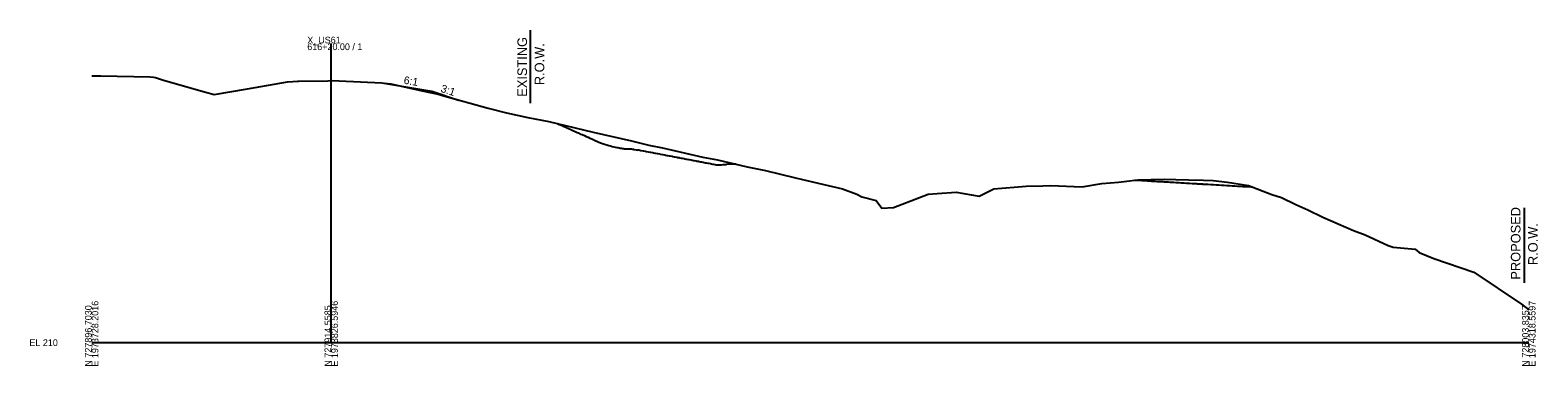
# Model space of a CAD drawing. Extents: x -26 to 1604, y -13 to 9623.
# Drawn here: x 974 to 1604, y 490 to 631 of the extents above; entities that cross this region are included whole.
import ezdxf

# ---------------------------------------------------------------- set-up
doc = ezdxf.new("R2010")
doc.units = 0
for name, color, linetype in [('Default', 7, 'Continuous'), ('Draft_XS_Grid', 7, 'Continuous'), ('DTM_X_GROUND', 7, 'Continuous'), ('SLOPE_STAKES_FILL', 7, 'Continuous'), ('XS_CELL', 7, 'Continuous'), ('XS_P_GROUND', 7, 'Continuous'), ('XS_P_ROW', 7, 'Continuous'), ('XS_P_TX_FS_BS', 7, 'Continuous'), ('XS_X_ROW', 7, 'Continuous')]:
    doc.layers.add(name, color=color, linetype=linetype)

msp = doc.modelspace()

# ---------------------------------------------------------------- linework, layer by layer
at = {"layer": 'DTM_X_GROUND'}
msp.add_lwpolyline([(1000, 611.51), (1003.78, 611.44), (1024.39, 611.01), (1025.78, 610.86), (1026.67, 610.77), (1030.01, 609.71), (1047.11, 604.73), (1051.11, 603.72), (1065, 606), (1081.75, 608.91), (1083.96, 609.12), (1085.87, 609.21), (1086.51, 609.24), (1098.56, 609.41), (1100.49, 609.44), (1103.32, 609.31), (1121.08, 608.53), (1123.5, 608.24), (1124.96, 608.06), (1137.92, 605.23), (1144.7, 603.77), (1146.52, 603.23), (1165.48, 597.91), (1173.2, 595.98), (1182.04, 594.12), (1190.91, 592.35), (1201.88, 589.7), (1209.38, 587.88), (1225.43, 584.35), (1232.56, 582.51), (1238.27, 581.32), (1255.12, 577.5), (1261.32, 576.32), (1273.61, 573.44), (1281.32, 571.87), (1293.79, 568.9), (1303.36, 566.61), (1313.47, 564.19), (1319.45, 562.08), (1321.48, 560.86), (1327.48, 559.43), (1329.84, 556.19), (1334.7, 556.44), (1349.17, 561.98), (1352.99, 562.24), (1360.98, 562.92), (1370.48, 561.14), (1376.65, 564.19), (1390.14, 565.32), (1397.15, 565.51), (1400.35, 565.62), (1413.46, 565.1), (1421.76, 566.43), (1428.74, 567.05), (1436.76, 567.96), (1447.97, 568.23), (1452.69, 568.22), (1457.9, 567.98), (1464.24, 567.9), (1468.26, 567.72), (1474.18, 567.04), (1482.92, 565.58), (1492.75, 561.94), (1496.71, 560.61), (1502.75, 557.67), (1507.81, 555.44), (1513.97, 552.44), (1526.87, 546.84), (1531.74, 545), (1541.29, 540.52), (1543.33, 539.94), (1552.54, 539.01), (1554.16, 537.62), (1560.3, 535.11), (1577.1, 529.46), (1596.98, 516.06), (1600, 513.78)], dxfattribs=at)
at = {"layer": 'XS_CELL'}
for p, q in [((1100, 500), (1100, 625)), ((1000, 500), (1100, 500)), ((1100, 500), (1600, 500))]:
    msp.add_line(p, q, dxfattribs=at)
at = {"layer": 'XS_P_GROUND'}
for points in [[(1122, 608.42), (1142, 605.09)], [(1142, 605.09), (1153.19, 601.36)], [(1194.64, 591.45), (1195.22, 591.19), (1195.25, 591.17), (1196.71, 590.52), (1196.85, 590.46), (1198.21, 589.85), (1198.44, 589.75), (1199.72, 589.18), (1200.04, 589.03), (1201.22, 588.51), (1201.63, 588.32), (1202.72, 587.84), (1203.23, 587.61), (1204.23, 587.16), (1204.82, 586.9), (1205.73, 586.49), (1206.42, 586.18), (1207.24, 585.82), (1208.02, 585.47), (1208.75, 585.14), (1209.61, 584.76), (1210.26, 584.47), (1211.21, 584.04), (1211.77, 583.79), (1212.8, 583.33), (1214.1, 582.92), (1215.03, 582.6), (1215.94, 582.35), (1216.62, 582.16), (1217.32, 581.98), (1217.99, 581.81), (1218.54, 581.69), (1219.18, 581.55), (1219.63, 581.46), (1220.26, 581.34), (1220.62, 581.28), (1221.24, 581.18), (1221.55, 581.14), (1222.16, 581.06), (1222.43, 581.03), (1223.04, 580.97), (1223.28, 580.96), (1223.88, 580.92), (1224.11, 580.91), (1224.71, 580.9), (1224.94, 580.9), (1225.53, 580.9), (1225.65, 580.88), (1226.27, 580.76), (1226.43, 580.73), (1227.27, 580.57), (1227.38, 580.55), (1227.94, 580.45)], [(1269.08, 574.5), (1268.34, 574.52), (1268.26, 574.52), (1267.24, 574.54), (1266.21, 574.57), (1266.17, 574.57), (1266.14, 574.57), (1264.97, 574.38), (1264.72, 574.35), (1263.84, 574.24), (1263.53, 574.22), (1262.77, 574.15), (1262.41, 574.13), (1261.73, 574.09), (1261.58, 574.09), (1261.34, 574.09), (1260.76, 574.2), (1260.33, 574.28), (1259.75, 574.39), (1259.33, 574.47), (1258.74, 574.58), (1258.33, 574.66), (1257.73, 574.77), (1257.33, 574.85), (1256.72, 574.97), (1256.33, 575.04), (1255.71, 575.16), (1255.32, 575.23), (1254.7, 575.35), (1254.32, 575.42), (1253.69, 575.54), (1253.32, 575.61), (1252.68, 575.74), (1252.32, 575.8), (1251.67, 575.93), (1251.32, 576), (1250.66, 576.12), (1250.31, 576.19), (1249.65, 576.31), (1249.31, 576.38), (1248.64, 576.5), (1248.31, 576.57), (1247.63, 576.7), (1247.31, 576.76), (1246.62, 576.89), (1246.31, 576.95), (1245.61, 577.08), (1245.3, 577.14), (1244.6, 577.27), (1244.3, 577.33), (1243.59, 577.47), (1243.3, 577.52), (1242.58, 577.66), (1242.3, 577.71), (1241.57, 577.85), (1241.3, 577.9), (1240.56, 578.04), (1240.29, 578.09), (1239.55, 578.23), (1239.29, 578.28), (1238.54, 578.43), (1238.29, 578.48), (1237.53, 578.62), (1237.29, 578.67), (1236.52, 578.81), (1236.29, 578.86), (1235.51, 579), (1235.28, 579.05), (1234.5, 579.2), (1234.28, 579.24), (1233.5, 579.39), (1233.28, 579.43), (1232.49, 579.58), (1232.28, 579.62), (1231.48, 579.77), (1231.28, 579.81), (1230.47, 579.96), (1230.27, 580), (1229.46, 580.16), (1229.27, 580.19), (1228.45, 580.35), (1228.27, 580.38), (1228, 580.43), (1227.94, 580.45)], [(1484.69, 564.92), (1483.95, 564.96), (1483.94, 564.96), (1482.84, 565.03), (1481.74, 565.09), (1481.73, 565.09), (1480.63, 565.16), (1480.62, 565.16), (1479.53, 565.22), (1479.51, 565.22), (1478.42, 565.29), (1478.39, 565.29), (1477.31, 565.35), (1477.28, 565.35), (1476.2, 565.42), (1476.17, 565.42), (1475.09, 565.48), (1475.06, 565.48), (1473.98, 565.55), (1473.95, 565.55), (1472.88, 565.61), (1472.84, 565.61), (1471.77, 565.68), (1471.73, 565.68), (1471.69, 565.68), (1470.62, 565.74), (1470.58, 565.75), (1469.51, 565.81), (1469.46, 565.81), (1468.4, 565.87), (1468.35, 565.88), (1467.29, 565.94), (1467.24, 565.94), (1466.18, 566), (1466.12, 566.01), (1465.07, 566.07), (1465.03, 566.07), (1464.41, 566.11), (1464.39, 566.11), (1463.95, 566.13), (1463.89, 566.14), (1462.84, 566.2), (1462.77, 566.2), (1461.73, 566.26), (1461.7, 566.26), (1461.24, 566.29), (1461.2, 566.29), (1460.62, 566.33), (1460.54, 566.33), (1459.51, 566.39), (1459.43, 566.4), (1458.4, 566.46), (1458.35, 566.46), (1457.74, 566.5), (1457.7, 566.5), (1457.29, 566.52), (1457.28, 566.52), (1457.16, 566.53), (1457.07, 566.53), (1456.18, 566.59), (1456.17, 566.59), (1456.05, 566.59), (1455.95, 566.6), (1455.07, 566.65), (1455.06, 566.65), (1454.94, 566.66), (1454.84, 566.66), (1453.96, 566.72), (1453.94, 566.72), (1453.84, 566.72), (1453.72, 566.73), (1452.85, 566.78), (1452.83, 566.78), (1452.73, 566.79), (1452.6, 566.8), (1451.74, 566.85), (1451.72, 566.85), (1451.63, 566.85), (1451.47, 566.86), (1450.63, 566.91), (1450.61, 566.91), (1450.52, 566.92), (1450.33, 566.93), (1449.51, 566.98), (1449.5, 566.98), (1449.41, 566.98), (1449.16, 567), (1448.4, 567.04), (1448.38, 567.04), (1448.31, 567.05), (1447.92, 567.07), (1447.29, 567.11), (1447.26, 567.11), (1447.2, 567.11), (1446.25, 567.17), (1446.18, 567.17), (1446.13, 567.17), (1446.1, 567.18), (1446.09, 567.18), (1445.07, 567.24), (1444.99, 567.24), (1444.99, 567.24), (1444, 567.3), (1443.96, 567.3), (1443.89, 567.3), (1443.88, 567.3), (1443.25, 567.34), (1443.23, 567.34), (1443.22, 567.34), (1443.22, 567.34), (1442.96, 567.36), (1442.95, 567.36), (1442.85, 567.36), (1442.85, 567.36), (1442.78, 567.37), (1442.78, 567.37), (1442.57, 567.38), (1442.56, 567.38), (1442.19, 567.4), (1442.18, 567.4), (1441.85, 567.42), (1441.84, 567.42), (1441.79, 567.43), (1441.79, 567.43), (1441.74, 567.43), (1441.74, 567.43), (1441.7, 567.43), (1441.7, 567.43), (1441.68, 567.43), (1441.68, 567.43), (1441.68, 567.43), (1441.68, 567.43), (1441.67, 567.43), (1441.67, 567.43), (1440.65, 567.49), (1440.63, 567.49), (1439.54, 567.56), (1439.52, 567.56), (1438.43, 567.62), (1438.41, 567.62), (1437.31, 567.69), (1437.3, 567.69), (1436.19, 567.75), (1436.18, 567.75), (1435.36, 567.8)]]:
    msp.add_lwpolyline(points, dxfattribs=at)
at = {"layer": 'XS_P_ROW'}
msp.add_line((1598, 556.27), (1598, 525), dxfattribs=at)
at = {"layer": 'XS_X_ROW'}
msp.add_line((1183, 630.55), (1183, 600), dxfattribs=at)

# ---------------------------------------------------------------- texts
at = {"layer": 'Default'}
msp.add_text('X', height=0.12, dxfattribs=at).set_placement((1141.96, 605.03))
at = {"layer": 'Draft_XS_Grid'}
msp.add_text('-', height=0.0001, dxfattribs=at).set_placement((1000, 500))
at = {"layer": 'SLOPE_STAKES_FILL'}
msp.add_text('X', height=0.12, dxfattribs=at).set_placement((1141.96, 605.03))
at = {"layer": 'XS_CELL'}
for s, p in [('X_US61', (1090, 625)), ('616+20.00 / 1', (1090, 622.2)), ('EL 210', (974, 498.6))]:
    msp.add_text(s, height=2.8, dxfattribs=at).set_placement(p)
for s, p in [('E 1973728.2016', (1002.8, 490)), ('E 1973826.5946', (1102.8, 490)), ('E 1974318.5597', (1602.8, 490)), ('N 727896.7030', (1000, 490)), ('N 727914.5585', (1100, 490)), ('N 728003.8357', (1600, 490))]:
    msp.add_text(s, height=2.8, rotation=90, dxfattribs=at).set_placement(p)
at = {"layer": 'XS_P_GROUND'}
for p in [(1121.96, 608.36), (1153.15, 601.3)]:
    msp.add_text('X', height=0.12, dxfattribs=at).set_placement(p)
at = {"layer": 'XS_P_ROW'}
for s, p in [('PROPOSED', (1596.52, 526.33)), ('R.O.W.', (1603.72, 532.4))]:
    msp.add_text(s, height=4, rotation=90, dxfattribs=at).set_placement(p)
at = {"layer": 'XS_P_TX_FS_BS'}
for s, rotation, p in [('6:1', 350.53766, (1130.1, 608.18)), ('3:1', 341.56507, (1145.45, 604.85))]:
    msp.add_text(s, height=3.24, rotation=rotation, dxfattribs=at).set_placement(p)
at = {"layer": 'XS_X_ROW'}
for s, p in [('EXISTING', (1181.75, 602.72)), ('R.O.W.', (1188.95, 607.56))]:
    msp.add_text(s, height=4, rotation=90, dxfattribs=at).set_placement(p)

doc.saveas('drawing.dxf')
